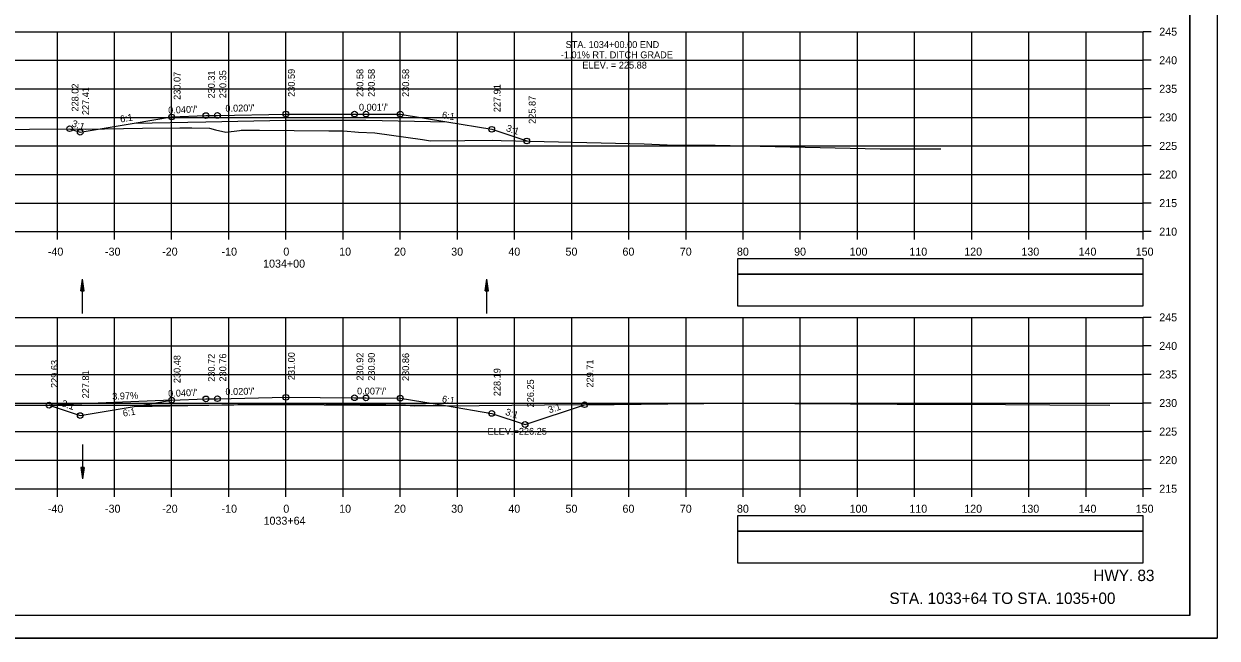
# Model space of a CAD drawing. Extents: x 1386544 to 1388153, y 379785 to 390999.
# Drawn here: x 1387313.8 to 1387522.6, y 386092.2 to 386199.7 of the extents above; entities that cross this region are included whole.
import ezdxf

# ---------------------------------------------------------------- set-up
doc = ezdxf.new("R2010")
doc.units = 0
for name, color, linetype in [('R_Alt Surface', 7, 'Continuous'), ('R_Axis', 7, 'Continuous'), ('R_Axis Annot', 7, 'Continuous'), ('R_Border', 7, 'Continuous'), ('R_Draft', 7, 'Continuous'), ('R_Drive', 7, 'Continuous'), ('R_Exist Surface', 7, 'Continuous'), ('R_Fin Surface', 7, 'Continuous'), ('R_Grid', 7, 'Continuous'), ('R_No Plot', 7, 'Continuous'), ('R_Water', 7, 'Continuous'), ('R_Xsect Elev', 7, 'Continuous'), ('R_Xsect Slope', 7, 'Continuous')]:
    doc.layers.add(name, color=color, linetype=linetype)

msp = doc.modelspace()

# ---------------------------------------------------------------- linework, layer by layer
at = {"layer": 'R_Alt Surface'}
for points in [[(1387333.11, 386182.3), (1387345.68, 386182.55), (1387359.68, 386182.83), (1387373.68, 386182.82), (1387387.85, 386182.54)], [(1387333.11, 386132.7), (1387345.68, 386132.96), (1387359.68, 386133.24), (1387373.68, 386133.14), (1387387.6, 386132.86)]]:
    msp.add_lwpolyline(points, dxfattribs=at)
at = {"layer": 'R_Axis'}
for p, q in [((1387509.68, 386163.32), (1387509.68, 386198.32)), ((1387511.08, 386198.32), (1387509.68, 386198.32)), ((1387511.08, 386193.32), (1387509.68, 386193.32)), ((1387511.08, 386188.32), (1387509.68, 386188.32)), ((1387511.08, 386183.32), (1387509.68, 386183.32)), ((1387511.08, 386178.32), (1387509.68, 386178.32)), ((1387511.08, 386173.32), (1387509.68, 386173.32)), ((1387511.08, 386168.32), (1387509.68, 386168.32)), ((1387209.68, 386163.32), (1387509.68, 386163.32)), ((1387319.68, 386161.92), (1387319.68, 386163.32)), ((1387329.68, 386161.92), (1387329.68, 386163.32)), ((1387339.68, 386161.92), (1387339.68, 386163.32)), ((1387349.68, 386161.92), (1387349.68, 386163.32)), ((1387359.68, 386161.92), (1387359.68, 386163.32)), ((1387369.68, 386161.92), (1387369.68, 386163.32)), ((1387379.68, 386161.92), (1387379.68, 386163.32)), ((1387389.68, 386161.92), (1387389.68, 386163.32)), ((1387399.68, 386161.92), (1387399.68, 386163.32)), ((1387409.68, 386161.92), (1387409.68, 386163.32)), ((1387419.68, 386161.92), (1387419.68, 386163.32)), ((1387429.68, 386161.92), (1387429.68, 386163.32)), ((1387439.68, 386161.92), (1387439.68, 386163.32)), ((1387449.68, 386161.92), (1387449.68, 386163.32)), ((1387459.68, 386161.92), (1387459.68, 386163.32)), ((1387469.68, 386161.92), (1387469.68, 386163.32)), ((1387479.68, 386161.92), (1387479.68, 386163.32)), ((1387489.68, 386161.92), (1387489.68, 386163.32)), ((1387499.68, 386161.92), (1387499.68, 386163.32)), ((1387509.68, 386161.92), (1387509.68, 386163.32)), ((1387511.08, 386163.32), (1387509.68, 386163.32)), ((1387509.68, 386118.32), (1387509.68, 386148.32)), ((1387511.08, 386148.32), (1387509.68, 386148.32)), ((1387511.08, 386143.32), (1387509.68, 386143.32)), ((1387511.08, 386138.32), (1387509.68, 386138.32)), ((1387511.08, 386133.32), (1387509.68, 386133.32)), ((1387511.08, 386128.32), (1387509.68, 386128.32)), ((1387511.08, 386123.32), (1387509.68, 386123.32)), ((1387209.68, 386118.32), (1387509.68, 386118.32)), ((1387319.68, 386116.92), (1387319.68, 386118.32)), ((1387329.68, 386116.92), (1387329.68, 386118.32)), ((1387339.68, 386116.92), (1387339.68, 386118.32)), ((1387349.68, 386116.92), (1387349.68, 386118.32)), ((1387359.68, 386116.92), (1387359.68, 386118.32)), ((1387369.68, 386116.92), (1387369.68, 386118.32)), ((1387379.68, 386116.92), (1387379.68, 386118.32)), ((1387389.68, 386116.92), (1387389.68, 386118.32)), ((1387399.68, 386116.92), (1387399.68, 386118.32)), ((1387409.68, 386116.92), (1387409.68, 386118.32)), ((1387419.68, 386116.92), (1387419.68, 386118.32)), ((1387429.68, 386116.92), (1387429.68, 386118.32)), ((1387439.68, 386116.92), (1387439.68, 386118.32)), ((1387449.68, 386116.92), (1387449.68, 386118.32)), ((1387459.68, 386116.92), (1387459.68, 386118.32)), ((1387469.68, 386116.92), (1387469.68, 386118.32)), ((1387479.68, 386116.92), (1387479.68, 386118.32)), ((1387489.68, 386116.92), (1387489.68, 386118.32)), ((1387499.68, 386116.92), (1387499.68, 386118.32)), ((1387509.68, 386116.92), (1387509.68, 386118.32)), ((1387511.08, 386118.32), (1387509.68, 386118.32))]:
    msp.add_line(p, q, dxfattribs=at)
at = {"layer": 'R_Axis Annot'}
for points in [[(1387438.7, 386155.87), (1387509.68, 386155.87), (1387509.68, 386158.58), (1387438.7, 386158.58)], [(1387438.7, 386150.34), (1387509.68, 386150.34), (1387509.68, 386155.87), (1387438.7, 386155.87)], [(1387438.7, 386110.87), (1387509.68, 386110.87), (1387509.68, 386113.58), (1387438.7, 386113.58)], [(1387438.7, 386105.34), (1387509.68, 386105.34), (1387509.68, 386110.87), (1387438.7, 386110.87)]]:
    msp.add_lwpolyline(points, close=True, dxfattribs=at)
at = {"layer": 'R_Border'}
for q in [(1387517.86, 386301.61), (1387201.68, 386096.15)]:
    msp.add_line((1387517.86, 386096.15), q, dxfattribs=at)
at = {"layer": 'R_Drive'}
msp.add_line((1387339.68, 386133.8), (1387318.23, 386132.95), dxfattribs=at)
at = {"layer": 'R_Exist Surface'}
for points in [[(1387307.37, 386181.2), (1387322.22, 386181.34), (1387324.59, 386181.28), (1387334.58, 386181.42), (1387341.09, 386181.49), (1387341.91, 386181.48), (1387343.24, 386181.48), (1387346.3, 386181.44), (1387347.33, 386181.14), (1387349.14, 386180.76), (1387351.55, 386181.05), (1387351.86, 386181.1), (1387355.04, 386181.08), (1387367.21, 386180.95), (1387367.81, 386180.95), (1387369.75, 386180.97), (1387372.36, 386180.75), (1387375.22, 386180.6), (1387383.6, 386179.43), (1387384.97, 386179.24), (1387391, 386179.3), (1387395.83, 386179.36), (1387397.36, 386179.29), (1387422.38, 386178.71), (1387427.72, 386178.45), (1387434.8, 386178.47), (1387463.64, 386177.82), (1387471.23, 386177.79), (1387473.05, 386177.8), (1387474.24, 386177.81)], [(1387302.57, 386132.95), (1387320.04, 386132.95), (1387324.36, 386132.96), (1387339.23, 386132.96), (1387346.21, 386132.97), (1387354.97, 386133.08), (1387361.07, 386133.07), (1387366.37, 386133), (1387372.66, 386132.93), (1387380.58, 386132.94), (1387382.24, 386132.81), (1387393.5, 386132.87), (1387404.92, 386132.98), (1387412.21, 386133.04), (1387417.11, 386133.07), (1387431.21, 386133.23), (1387432.81, 386133.23), (1387441.32, 386133.28), (1387448.7, 386133.23), (1387450.31, 386133.23), (1387466.64, 386133.14), (1387471.09, 386133.11), (1387485.57, 386133.04), (1387493.34, 386132.99), (1387503.85, 386132.93)]]:
    msp.add_lwpolyline(points, dxfattribs=at)
at = {"layer": 'R_Fin Surface'}
for points in [[(1387321.83, 386181.34), (1387323.68, 386180.72), (1387333.11, 386182.3), (1387339.68, 386183.39), (1387345.68, 386183.63), (1387347.68, 386183.67), (1387359.68, 386183.91), (1387371.68, 386183.9), (1387373.68, 386183.9), (1387379.68, 386183.9), (1387387.85, 386182.54), (1387395.68, 386181.23), (1387401.81, 386179.19)], [(1387318.23, 386132.95), (1387323.68, 386131.13), (1387333.11, 386132.7), (1387339.68, 386133.8), (1387345.68, 386134.04), (1387347.68, 386134.08), (1387359.68, 386134.32), (1387371.68, 386134.24), (1387373.68, 386134.22), (1387379.68, 386134.18), (1387387.6, 386132.86), (1387395.68, 386131.51), (1387401.52, 386129.56), (1387411.93, 386133.03)]]:
    msp.add_lwpolyline(points, dxfattribs=at)
at = {"layer": 'R_Grid'}
for p, q in [((1387209.68, 386198.32), (1387509.68, 386198.32)), ((1387319.68, 386163.32), (1387319.68, 386198.32)), ((1387329.68, 386163.32), (1387329.68, 386198.32)), ((1387339.68, 386163.32), (1387339.68, 386198.32)), ((1387349.68, 386163.32), (1387349.68, 386198.32)), ((1387359.68, 386163.32), (1387359.68, 386198.32)), ((1387369.68, 386163.32), (1387369.68, 386198.32)), ((1387379.68, 386163.32), (1387379.68, 386198.32)), ((1387389.68, 386163.32), (1387389.68, 386198.32)), ((1387399.68, 386163.32), (1387399.68, 386198.32)), ((1387409.68, 386163.32), (1387409.68, 386198.32)), ((1387419.68, 386163.32), (1387419.68, 386198.32)), ((1387429.68, 386163.32), (1387429.68, 386198.32)), ((1387439.68, 386163.32), (1387439.68, 386198.32)), ((1387449.68, 386163.32), (1387449.68, 386198.32)), ((1387459.68, 386163.32), (1387459.68, 386198.32)), ((1387469.68, 386163.32), (1387469.68, 386198.32)), ((1387479.68, 386163.32), (1387479.68, 386198.32)), ((1387489.68, 386163.32), (1387489.68, 386198.32)), ((1387499.68, 386163.32), (1387499.68, 386198.32)), ((1387509.68, 386163.32), (1387509.68, 386198.32)), ((1387209.68, 386193.32), (1387509.68, 386193.32)), ((1387209.68, 386188.32), (1387509.68, 386188.32)), ((1387209.68, 386183.32), (1387509.68, 386183.32)), ((1387209.68, 386178.32), (1387509.68, 386178.32)), ((1387209.68, 386173.32), (1387509.68, 386173.32)), ((1387209.68, 386168.32), (1387509.68, 386168.32)), ((1387209.68, 386163.32), (1387509.68, 386163.32)), ((1387209.68, 386148.32), (1387509.68, 386148.32)), ((1387319.68, 386118.32), (1387319.68, 386148.32)), ((1387329.68, 386118.32), (1387329.68, 386148.32)), ((1387339.68, 386118.32), (1387339.68, 386148.32)), ((1387349.68, 386118.32), (1387349.68, 386148.32)), ((1387359.68, 386118.32), (1387359.68, 386148.32)), ((1387369.68, 386118.32), (1387369.68, 386148.32)), ((1387379.68, 386118.32), (1387379.68, 386148.32)), ((1387389.68, 386118.32), (1387389.68, 386148.32)), ((1387399.68, 386118.32), (1387399.68, 386148.32)), ((1387409.68, 386118.32), (1387409.68, 386148.32)), ((1387419.68, 386118.32), (1387419.68, 386148.32)), ((1387429.68, 386118.32), (1387429.68, 386148.32)), ((1387439.68, 386118.32), (1387439.68, 386148.32)), ((1387449.68, 386118.32), (1387449.68, 386148.32)), ((1387459.68, 386118.32), (1387459.68, 386148.32)), ((1387469.68, 386118.32), (1387469.68, 386148.32)), ((1387479.68, 386118.32), (1387479.68, 386148.32)), ((1387489.68, 386118.32), (1387489.68, 386148.32)), ((1387499.68, 386118.32), (1387499.68, 386148.32)), ((1387509.68, 386118.32), (1387509.68, 386148.32)), ((1387209.68, 386143.32), (1387509.68, 386143.32)), ((1387209.68, 386138.32), (1387509.68, 386138.32)), ((1387209.68, 386133.32), (1387509.68, 386133.32)), ((1387209.68, 386128.32), (1387509.68, 386128.32)), ((1387209.68, 386123.32), (1387509.68, 386123.32)), ((1387209.68, 386118.32), (1387509.68, 386118.32))]:
    msp.add_line(p, q, dxfattribs=at)
at = {"layer": 'R_No Plot'}
msp.add_line((1387189.28, 386092.17), (1387522.61, 386092.17), dxfattribs=at)
for points in [[(1387189.27, 386305.5), (1387522.61, 386305.5), (1387522.61, 386092.17), (1387189.27, 386092.17)], [(1387435.6, 386301.61), (1387455.22, 386301.61), (1387455.22, 386291.73), (1387471.33, 386291.73), (1387494.53, 386291.73), (1387494.53, 386267.4), (1387517.86, 386267.4), (1387517.86, 386096.15), (1387201.68, 386096.15), (1387201.68, 386301.61)]]:
    msp.add_lwpolyline(points, close=True, dxfattribs=at)
for centre in [(1387339.68, 386183.39), (1387345.68, 386183.63), (1387347.68, 386183.67), (1387359.68, 386183.91), (1387371.68, 386183.9), (1387373.68, 386183.9), (1387379.68, 386183.9), (1387321.83, 386181.34), (1387323.68, 386180.72), (1387395.68, 386181.23), (1387401.81, 386179.19), (1387318.23, 386132.95), (1387339.68, 386133.8), (1387345.68, 386134.04), (1387347.68, 386134.08), (1387359.68, 386134.32), (1387371.68, 386134.24), (1387373.68, 386134.22), (1387379.68, 386134.18), (1387411.93, 386133.03), (1387323.68, 386131.13), (1387395.68, 386131.51), (1387401.52, 386129.56)]:
    msp.add_circle(centre, 0.5, dxfattribs=at)
at = {"layer": 'R_Water'}
for p, q in [((1387323.8, 386152.98), (1387324.1, 386154.98)), ((1387323.8, 386152.98), (1387324.1, 386154.98)), ((1387323.85, 386152.98), (1387324.1, 386154.65)), ((1387323.85, 386152.98), (1387324.1, 386154.65)), ((1387323.9, 386152.98), (1387324.1, 386154.3)), ((1387323.9, 386152.98), (1387324.1, 386154.3)), ((1387323.95, 386152.98), (1387324.1, 386153.97)), ((1387323.95, 386152.98), (1387324.1, 386153.97)), ((1387324.1, 386148.98), (1387324.1, 386154.98)), ((1387324.4, 386152.98), (1387324.1, 386154.98)), ((1387324.4, 386152.98), (1387324.1, 386154.98)), ((1387324.35, 386152.98), (1387324.1, 386154.65)), ((1387324.35, 386152.98), (1387324.1, 386154.65)), ((1387324.3, 386152.98), (1387324.1, 386154.3)), ((1387324.3, 386152.98), (1387324.1, 386154.3)), ((1387324.25, 386152.98), (1387324.1, 386153.97)), ((1387324.25, 386152.98), (1387324.1, 386153.97)), ((1387394.53, 386152.98), (1387394.83, 386154.98)), ((1387394.53, 386152.98), (1387394.83, 386154.98)), ((1387394.58, 386152.98), (1387394.83, 386154.65)), ((1387394.58, 386152.98), (1387394.83, 386154.65)), ((1387394.63, 386152.98), (1387394.83, 386154.3)), ((1387394.63, 386152.98), (1387394.83, 386154.3)), ((1387394.68, 386152.98), (1387394.83, 386153.97)), ((1387394.68, 386152.98), (1387394.83, 386153.97)), ((1387394.83, 386148.98), (1387394.83, 386154.98)), ((1387395.13, 386152.98), (1387394.83, 386154.98)), ((1387395.13, 386152.98), (1387394.83, 386154.98)), ((1387395.08, 386152.98), (1387394.83, 386154.65)), ((1387395.08, 386152.98), (1387394.83, 386154.65)), ((1387395.03, 386152.98), (1387394.83, 386154.3)), ((1387395.03, 386152.98), (1387394.83, 386154.3)), ((1387394.98, 386152.98), (1387394.83, 386153.97)), ((1387394.98, 386152.98), (1387394.83, 386153.97)), ((1387323.8, 386152.98), (1387324.4, 386152.98)), ((1387323.8, 386152.98), (1387324.4, 386152.98)), ((1387324, 386152.98), (1387324.1, 386153.63)), ((1387324, 386152.98), (1387324.1, 386153.63)), ((1387324.05, 386152.98), (1387324.1, 386153.3)), ((1387324.05, 386152.98), (1387324.1, 386153.3)), ((1387324.19, 386152.98), (1387324.1, 386153.63)), ((1387324.19, 386152.98), (1387324.1, 386153.63)), ((1387324.14, 386152.98), (1387324.1, 386153.3)), ((1387324.14, 386152.98), (1387324.1, 386153.3)), ((1387394.53, 386152.98), (1387395.13, 386152.98)), ((1387394.53, 386152.98), (1387395.13, 386152.98)), ((1387394.73, 386152.98), (1387394.83, 386153.63)), ((1387394.73, 386152.98), (1387394.83, 386153.63)), ((1387394.78, 386152.98), (1387394.83, 386153.3)), ((1387394.78, 386152.98), (1387394.83, 386153.3)), ((1387394.93, 386152.98), (1387394.83, 386153.63)), ((1387394.93, 386152.98), (1387394.83, 386153.63)), ((1387394.87, 386152.98), (1387394.83, 386153.3)), ((1387394.87, 386152.98), (1387394.83, 386153.3)), ((1387324.1, 386126.06), (1387324.1, 386120.06)), ((1387323.8, 386122.06), (1387324.1, 386120.06)), ((1387324.4, 386122.06), (1387323.8, 386122.06)), ((1387323.8, 386122.06), (1387324.1, 386120.06)), ((1387324.4, 386122.06), (1387323.8, 386122.06)), ((1387323.85, 386122.06), (1387324.1, 386120.39)), ((1387323.85, 386122.06), (1387324.1, 386120.39)), ((1387323.9, 386122.06), (1387324.1, 386120.74)), ((1387323.9, 386122.06), (1387324.1, 386120.74)), ((1387323.95, 386122.06), (1387324.1, 386121.07)), ((1387323.95, 386122.06), (1387324.1, 386121.07)), ((1387324, 386122.06), (1387324.1, 386121.41)), ((1387324, 386122.06), (1387324.1, 386121.41)), ((1387324.05, 386122.06), (1387324.1, 386121.74)), ((1387324.05, 386122.06), (1387324.1, 386121.74)), ((1387324.4, 386122.06), (1387324.1, 386120.06)), ((1387324.19, 386122.06), (1387324.1, 386121.41)), ((1387324.3, 386122.06), (1387324.1, 386120.74)), ((1387324.35, 386122.06), (1387324.1, 386120.39)), ((1387324.25, 386122.06), (1387324.1, 386121.07)), ((1387324.14, 386122.06), (1387324.1, 386121.74)), ((1387324.4, 386122.06), (1387324.1, 386120.06)), ((1387324.19, 386122.06), (1387324.1, 386121.41)), ((1387324.3, 386122.06), (1387324.1, 386120.74)), ((1387324.35, 386122.06), (1387324.1, 386120.39)), ((1387324.25, 386122.06), (1387324.1, 386121.07)), ((1387324.14, 386122.06), (1387324.1, 386121.74))]:
    msp.add_line(p, q, dxfattribs=at)

# ---------------------------------------------------------------- texts
at = {"layer": 'R_Axis Annot'}
for s, p in [('245', (1387512.48, 386197.62)), ('240', (1387512.48, 386192.62)), ('235', (1387512.48, 386187.62)), ('230', (1387512.48, 386182.62)), ('225', (1387512.48, 386177.62)), ('220', (1387512.48, 386172.62)), ('215', (1387512.48, 386167.62)), ('210', (1387512.48, 386162.62)), ('-40', (1387318.02, 386159.12)), ('-30', (1387328.02, 386159.12)), ('-20', (1387338.02, 386159.12)), ('-10', (1387348.41, 386159.12)), ('0', (1387359.22, 386159.12)), ('10', (1387368.99, 386159.12)), ('20', (1387378.59, 386159.12)), ('30', (1387388.59, 386159.12)), ('40', (1387398.59, 386159.12)), ('50', (1387408.59, 386159.12)), ('60', (1387418.56, 386159.12)), ('70', (1387428.59, 386159.12)), ('80', (1387438.59, 386159.12)), ('90', (1387448.59, 386159.12)), ('100', (1387458.3, 386159.12)), ('110', (1387468.76, 386159.12)), ('120', (1387478.36, 386159.12)), ('130', (1387488.36, 386159.12)), ('140', (1387498.36, 386159.12)), ('150', (1387508.36, 386159.12)), ('1034+00', (1387355.68, 386157.02)), ('245', (1387512.48, 386147.62)), ('240', (1387512.48, 386142.62)), ('235', (1387512.48, 386137.62)), ('230', (1387512.48, 386132.62)), ('225', (1387512.48, 386127.62)), ('220', (1387512.48, 386122.62)), ('215', (1387512.48, 386117.62)), ('-40', (1387318.02, 386114.12)), ('-30', (1387328.02, 386114.12)), ('-20', (1387338.02, 386114.12)), ('-10', (1387348.41, 386114.12)), ('0', (1387359.22, 386114.12)), ('10', (1387368.99, 386114.12)), ('20', (1387378.59, 386114.12)), ('30', (1387388.59, 386114.12)), ('40', (1387398.59, 386114.12)), ('50', (1387408.59, 386114.12)), ('60', (1387418.56, 386114.12)), ('70', (1387428.59, 386114.12)), ('80', (1387438.59, 386114.12)), ('90', (1387448.59, 386114.12)), ('100', (1387458.3, 386114.12)), ('110', (1387468.76, 386114.12)), ('120', (1387478.36, 386114.12)), ('130', (1387488.36, 386114.12)), ('140', (1387498.36, 386114.12)), ('150', (1387508.36, 386114.12)), ('1033+64', (1387355.76, 386112.02))]:
    msp.add_text(s, height=1.4, dxfattribs=at).set_placement(p)
at = {"layer": 'R_Draft'}
for s, p in [('HWY. 83', (1387500.94, 386102.15)), ('STA. 1033+64 TO STA. 1035+00', (1387465.27, 386098.15))]:
    msp.add_text(s, height=2, dxfattribs=at).set_placement(p)
at = {"layer": 'R_Xsect Elev'}
for s, p in [('STA. 1034+00.00 END ', (1387408.62, 386195.47)), ('-1.01% RT. DITCH GRADE', (1387407.77, 386193.67)), ('ELEV. = 225.88', (1387411.54, 386191.87)), ('ELEV.=226.25', (1387394.94, 386127.77))]:
    msp.add_text(s, height=1.2, dxfattribs=at).set_placement(p)
for s, rotation, p in [('230.31', 90, (1387347.23, 386186.63)), ('230.35', 90, (1387349.23, 386186.67)), ('230.59', 90, (1387361.23, 386186.91)), ('230.58', 90, (1387373.23, 386186.9)), ('230.58', 90, (1387375.23, 386186.9)), ('230.58', 90, (1387381.23, 386186.9)), ('230.07', 90, (1387341.23, 386186.39)), ('228.02', 90, (1387323.38, 386184.34)), ('227.41', 90, (1387325.23, 386183.72)), ('227.91', 90, (1387397.23, 386184.23)), ('225.87', 90, (1387403.36, 386182.19)), ('230.48', 90, (1387341.23, 386136.8)), ('230.72', 90, (1387347.23, 386137.04)), ('230.76', 90, (1387349.23, 386137.08)), ('231.00', 90, (1387361.23, 386137.32)), ('230.92', 90, (1387373.23, 386137.24)), ('230.90', 90, (1387375.23, 386137.22)), ('230.86', 90, (1387381.23, 386137.18)), ('229.63', 90, (1387319.78, 386135.95)), ('228.19', 90, (1387397.23, 386134.51)), ('229.71', 90, (1387413.48, 386136.03)), ('227.81', 90, (1387325.23, 386134.13)), ('226.25', 90, (1387403.07, 386132.56)), ('3.97%', 2.2717, (1387329.3, 386133.89))]:
    msp.add_text(s, height=1.2, rotation=rotation, dxfattribs=at).set_placement(p)
at = {"layer": 'R_Xsect Slope'}
for s, rotation, p in [("0.040'/'", 2.2906, (1387339.09, 386183.97)), ("0.020'/'", 1.1458, (1387349.1, 386184.3)), ("0.001'/'", 359.9615, (1387372.45, 386184.5)), ('6:1', 9.4623, (1387330.75, 386182.41)), ('6:1', 350.5377, (1387386.91, 386183.2)), ('3:1', 341.5651, (1387322.12, 386181.77)), ('3:1', 341.5651, (1387398.11, 386180.95)), ("0.040'/'", 2.2906, (1387339.09, 386134.38)), ("0.020'/'", 1.1458, (1387349.1, 386134.71)), ("0.007'/'", 359.604, (1387372.12, 386134.83)), ('3:1', 341.5651, (1387320.32, 386132.78)), ('6:1', 350.5377, (1387386.91, 386133.48)), ('3:1', 18.4349, (1387405.78, 386131.51)), ('6:1', 9.4623, (1387331.23, 386130.93)), ('3:1', 341.5651, (1387397.97, 386131.28))]:
    msp.add_text(s, height=1.2, rotation=rotation, dxfattribs=at).set_placement(p)

doc.saveas('drawing.dxf')
